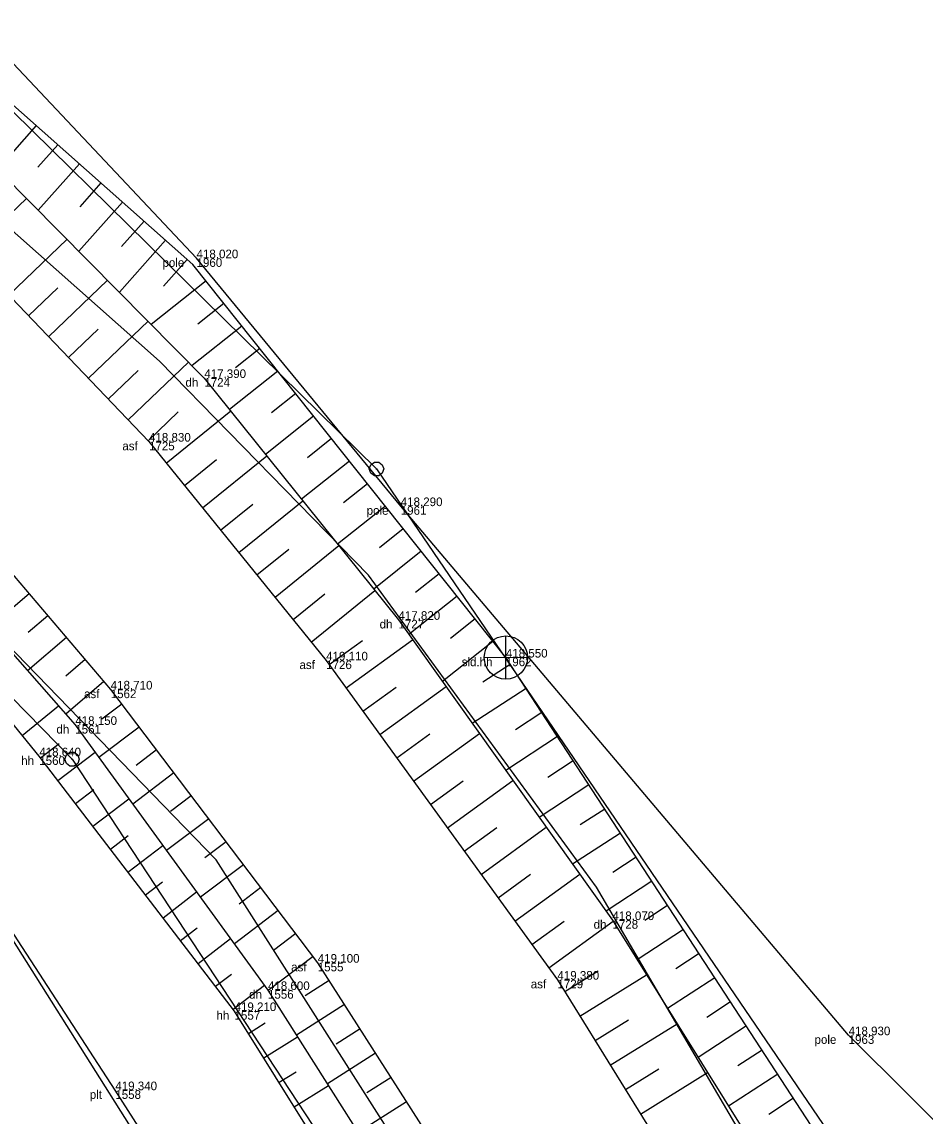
# Model space of a CAD drawing. Extents: x -747792 to -745414, y -1093712 to -1091463.
# Drawn here: x -746733.26 to -746701.9, y -1092442.69 to -1092404.68 of the extents above; entities that cross this region are included whole.
import ezdxf

# ---------------------------------------------------------------- set-up
doc = ezdxf.new("R2010")
doc.units = 0
for name, color, linetype in [('Doplňující texty', 7, 'Continuous'), ('Hladina', 7, 'Continuous'), ('Nezařazené objekty', 7, 'Continuous'), ('Nivelační značky_hrany', 7, 'Continuous'), ('Pracovní_bod JDTM STC_VC - výška', 7, 'Continuous'), ('Pracovní_bod PPBP', 7, 'Continuous'), ('Rozhraní ploch', 7, 'Continuous'), ('Stromy_porost', 7, 'Continuous'), ('Výškopis', 7, 'Continuous'), ('Čísla popisná_parcelní', 7, 'Continuous')]:
    doc.layers.add(name, color=color, linetype=linetype)

msp = doc.modelspace()

# ---------------------------------------------------------------- linework, layer by layer
at = {"layer": 'Doplňující texty'}
for points in [[(-746720.875, -1092419.97), (-746720.75, -1092420.065), (-746720.7, -1092420.21), (-746720.75, -1092420.355), (-746720.875, -1092420.45), (-746721.025, -1092420.45), (-746721.15, -1092420.355), (-746721.2, -1092420.21), (-746721.15, -1092420.065), (-746721.025, -1092419.97)], [(-746731.445, -1092430.05), (-746731.32, -1092430.145), (-746731.27, -1092430.29), (-746731.32, -1092430.435), (-746731.445, -1092430.53), (-746731.595, -1092430.53), (-746731.72, -1092430.435), (-746731.77, -1092430.29), (-746731.72, -1092430.145), (-746731.595, -1092430.05)]]:
    msp.add_lwpolyline(points, close=True, dxfattribs=at)
for points in [[(-746720.975, -1092420.21), (-746720.925, -1092420.21)], [(-746731.545, -1092430.29), (-746731.495, -1092430.29)]]:
    msp.add_lwpolyline(points, dxfattribs=at)
at = {"layer": 'Hladina'}
for p, q in [((-746727.2, -1092412.89), (-746727.2, -1092412.89)), ((-746726.93, -1092417.05), (-746726.93, -1092417.05)), ((-746728.85, -1092419.26), (-746728.85, -1092419.26)), ((-746720.11, -1092421.5), (-746720.11, -1092421.5)), ((-746720.19, -1092425.45), (-746720.19, -1092425.45)), ((-746716.46, -1092426.76), (-746716.46, -1092426.76)), ((-746722.7, -1092426.86), (-746722.7, -1092426.86)), ((-746730.18, -1092427.87), (-746730.18, -1092427.87)), ((-746731.41, -1092429.1), (-746731.41, -1092429.1)), ((-746732.66, -1092430.19), (-746732.66, -1092430.19)), ((-746712.76, -1092435.88), (-746712.76, -1092435.88)), ((-746722.99, -1092437.36), (-746722.99, -1092437.36)), ((-746714.67, -1092437.95), (-746714.67, -1092437.95)), ((-746724.72, -1092438.31), (-746724.72, -1092438.31)), ((-746725.88, -1092439.04), (-746725.88, -1092439.04)), ((-746704.56, -1092439.88), (-746704.56, -1092439.88)), ((-746730.02, -1092441.79), (-746730.02, -1092441.79))]:
    msp.add_line(p, q, dxfattribs=at)
at = {"layer": 'Nezařazené objekty'}
msp.add_lwpolyline([(-746689.71, -1092511.48), (-746691.52, -1092507.42), (-746698.75, -1092492.3), (-746705.08, -1092480.78), (-746714.94, -1092465.39), (-746724.32, -1092450.72), (-746730.02, -1092441.79), (-746735.89, -1092432.77), (-746739.69, -1092426.99), (-746754.65, -1092434.36)], dxfattribs=at)
at = {"layer": 'Nivelační značky_hrany'}
for points in [[(-746808.227, -1092357.17), (-746797.53, -1092364.29), (-746787.69, -1092371.13), (-746776.62, -1092378.78), (-746765.54, -1092386.79), (-746755.3, -1092394.62), (-746745.57, -1092402.66), (-746737.91, -1092409.79), (-746728.85, -1092419.26), (-746722.7, -1092426.86), (-746714.67, -1092437.95), (-746707.62, -1092449.35), (-746700.44, -1092461.3), (-746693.84, -1092472.82), (-746684.01, -1092490.2), (-746680.08, -1092497.02)], [(-746686.53, -1092499.12), (-746692.76, -1092488.22), (-746699.39, -1092476.65), (-746707.7, -1092462.24), (-746717.59, -1092445.81), (-746722.99, -1092437.36), (-746730.18, -1092427.87), (-746736.68, -1092420.23), (-746741.31, -1092415.91)]]:
    msp.add_lwpolyline(points, dxfattribs=at)
at = {"layer": 'Pracovní_bod JDTM STC_VC - výška'}
msp.add_lwpolyline([(-746666.48, -1092509.53), (-746671.18, -1092501.38), (-746679.28, -1092488.1), (-746683.01, -1092480.66), (-746691.02, -1092465.89), (-746695.91, -1092457.38), (-746697.67, -1092451.5), (-746700.29, -1092444.13), (-746704.56, -1092439.88), (-746720.11, -1092421.5), (-746727.2, -1092412.89), (-746738.25, -1092401.15), (-746749.37, -1092389.72), (-746764.79, -1092376.86), (-746776.64, -1092368.43), (-746787.43, -1092361.47), (-746799.53, -1092355.13), (-746817.34, -1092343.1), (-746824.75, -1092337.86), (-746838.2, -1092329.38), (-746851.64, -1092319.28)], dxfattribs=at)
at = {"layer": 'Pracovní_bod PPBP'}
for points in [[(-746676.31, -1092494.93), (-746679.28, -1092488.1), (-746684.61, -1092481.19), (-746692.58, -1092466.75), (-746703.9, -1092446.01), (-746716.46, -1092426.76), (-746727.325, -1092413.107), (-746739.95, -1092401.9), (-746747.98, -1092394.64), (-746752.03, -1092391.71), (-746753.83, -1092389.76), (-746758.64, -1092386.23), (-746765.82, -1092381.07), (-746787.5, -1092365.52), (-746806.41, -1092354.03)], [(-746807.12, -1092355.24), (-746796.58, -1092362.79), (-746786.63, -1092368.73), (-746775.02, -1092376.93), (-746764.6, -1092384.11), (-746753.89, -1092392.74), (-746744.6, -1092400.27), (-746734.99, -1092408.91), (-746726.93, -1092417.05), (-746720.19, -1092425.45), (-746712.76, -1092435.88), (-746705, -1092448.32), (-746698.55, -1092460.04), (-746691.76, -1092472.37), (-746682.53, -1092488.74), (-746678.42, -1092495.91)], [(-746732.762, -1092408.281), (-746734.11, -1092409.799)], [(-746732.014, -1092408.945), (-746732.709, -1092409.728)], [(-746731.266, -1092409.608), (-746732.7, -1092411.223)], [(-746730.518, -1092410.272), (-746731.256, -1092411.104)], [(-746735.103, -1092412.724), (-746733.106, -1092410.813)], [(-746729.771, -1092410.936), (-746731.289, -1092412.647)], [(-746729.023, -1092411.6), (-746729.804, -1092412.48)], [(-746733.721, -1092414.169), (-746731.698, -1092412.234)], [(-746728.275, -1092412.264), (-746729.879, -1092414.071)], [(-746727.527, -1092412.928), (-746728.351, -1092413.856)], [(-746732.338, -1092415.614), (-746730.291, -1092413.656)], [(-746726.87, -1092413.678), (-746728.771, -1092415.191)], [(-746733.029, -1092414.891), (-746732.012, -1092413.918)], [(-746726.248, -1092414.461), (-746727.156, -1092415.183)], [(-746731.647, -1092416.337), (-746730.617, -1092415.351)], [(-746730.956, -1092417.059), (-746728.884, -1092415.077)], [(-746725.625, -1092415.243), (-746727.356, -1092416.62)], [(-746725.002, -1092416.026), (-746725.841, -1092416.693)], [(-746729.573, -1092418.504), (-746727.476, -1092416.498)], [(-746730.264, -1092417.782), (-746729.222, -1092416.785)], [(-746724.38, -1092416.808), (-746726.055, -1092418.141)], [(-746742.5, -1092417.34), (-746737.93, -1092421.69), (-746731.41, -1092429.1), (-746724.72, -1092438.31), (-746719.2, -1092447.02), (-746709.7, -1092462.98), (-746701.01, -1092477.63), (-746694.64, -1092489.15), (-746688.39, -1092500.4)], [(-746723.757, -1092417.591), (-746724.593, -1092418.256)], [(-746728.882, -1092419.227), (-746727.836, -1092418.226)], [(-746728.25, -1092420.002), (-746726.014, -1092418.192)], [(-746723.134, -1092418.373), (-746724.803, -1092419.701)], [(-746689.26, -1092500.91), (-746696.41, -1092489.76), (-746702.72, -1092478.69), (-746711.35, -1092464.17), (-746720.24, -1092448.07), (-746725.88, -1092439.04), (-746732.66, -1092430.19), (-746738.76, -1092422.69), (-746743.86, -1092418.82)], [(-746722.512, -1092419.155), (-746723.344, -1092419.818)], [(-746727.621, -1092420.779), (-746726.504, -1092419.876)], [(-746726.992, -1092421.556), (-746724.762, -1092419.752)], [(-746721.889, -1092419.938), (-746723.551, -1092421.261)], [(-746721.266, -1092420.72), (-746722.096, -1092421.381)], [(-746726.363, -1092422.334), (-746725.249, -1092421.433)], [(-746725.734, -1092423.111), (-746723.51, -1092421.312)], [(-746720.644, -1092421.503), (-746722.3, -1092422.821)], [(-746720.021, -1092422.285), (-746720.847, -1092422.943)], [(-746725.104, -1092423.889), (-746723.994, -1092422.99)], [(-746724.475, -1092424.666), (-746722.259, -1092422.872)], [(-746719.398, -1092423.068), (-746721.048, -1092424.381)], [(-746718.776, -1092423.85), (-746719.599, -1092424.505)], [(-746723.217, -1092426.221), (-746721.007, -1092424.432)], [(-746733.008, -1092424.546), (-746734.386, -1092425.718)], [(-746723.846, -1092425.443), (-746722.74, -1092424.548)], [(-746718.153, -1092424.633), (-746719.825, -1092425.963)], [(-746732.36, -1092425.307), (-746733.043, -1092425.888)], [(-746717.53, -1092425.415), (-746718.387, -1092426.097)], [(-746731.712, -1092426.069), (-746733.065, -1092427.22)], [(-746722.596, -1092427.004), (-746721.441, -1092426.167)], [(-746722.009, -1092427.814), (-746719.698, -1092426.14)], [(-746716.907, -1092426.198), (-746718.662, -1092427.594)], [(-746731.064, -1092426.831), (-746731.734, -1092427.401)], [(-746716.306, -1092426.996), (-746717.256, -1092427.615)], [(-746730.416, -1092427.592), (-746731.743, -1092428.721)], [(-746721.423, -1092428.624), (-746720.27, -1092427.789)], [(-746720.836, -1092429.434), (-746718.538, -1092427.769)], [(-746715.76, -1092427.833), (-746717.625, -1092429.05)], [(-746733.25, -1092429.465), (-746731.99, -1092428.44)], [(-746729.796, -1092428.376), (-746730.486, -1092428.899)], [(-746715.213, -1092428.671), (-746716.129, -1092429.268)], [(-746729.192, -1092429.174), (-746730.588, -1092430.231)], [(-746720.25, -1092430.244), (-746719.104, -1092429.414)], [(-746719.663, -1092431.054), (-746717.377, -1092429.398)], [(-746732.62, -1092430.242), (-746731.965, -1092429.74)], [(-746714.667, -1092429.508), (-746716.464, -1092430.681)], [(-746732.012, -1092431.036), (-746730.722, -1092430.047)], [(-746728.588, -1092429.971), (-746729.295, -1092430.506)], [(-746714.12, -1092430.346), (-746715.002, -1092430.921)], [(-746727.985, -1092430.768), (-746729.413, -1092431.85)], [(-746731.404, -1092431.829), (-746730.769, -1092431.343)], [(-746719.077, -1092431.864), (-746717.937, -1092431.038)], [(-746718.491, -1092432.674), (-746716.217, -1092431.027)], [(-746713.574, -1092431.183), (-746715.303, -1092432.311)], [(-746730.796, -1092432.623), (-746729.546, -1092431.666)], [(-746727.381, -1092431.565), (-746728.103, -1092432.112)], [(-746713.028, -1092432.021), (-746713.875, -1092432.573)], [(-746726.777, -1092432.362), (-746728.237, -1092433.468)], [(-746717.904, -1092433.484), (-746716.77, -1092432.663)], [(-746717.318, -1092434.294), (-746715.056, -1092432.656)], [(-746712.481, -1092432.858), (-746714.141, -1092433.941)], [(-746730.188, -1092433.417), (-746729.573, -1092432.946)], [(-746726.173, -1092433.159), (-746726.911, -1092433.718)], [(-746729.58, -1092434.211), (-746728.37, -1092433.285)], [(-746725.569, -1092433.956), (-746727.061, -1092435.087)], [(-746711.935, -1092433.696), (-746712.748, -1092434.226)], [(-746716.731, -1092435.103), (-746715.604, -1092434.287)], [(-746716.145, -1092435.913), (-746713.896, -1092434.285)], [(-746728.971, -1092435.005), (-746728.377, -1092434.549)], [(-746724.965, -1092434.753), (-746725.719, -1092435.324)], [(-746711.388, -1092434.533), (-746712.98, -1092435.572)], [(-746728.363, -1092435.799), (-746727.195, -1092434.903)], [(-746710.842, -1092435.371), (-746711.636, -1092435.889)], [(-746724.361, -1092435.55), (-746725.886, -1092436.705)], [(-746715.558, -1092436.723), (-746714.437, -1092435.912)], [(-746714.972, -1092437.533), (-746712.738, -1092435.916)], [(-746727.755, -1092436.592), (-746727.181, -1092436.152)], [(-746710.295, -1092436.208), (-746711.902, -1092437.256)], [(-746727.147, -1092437.386), (-746726.019, -1092436.522)], [(-746723.757, -1092436.347), (-746724.528, -1092436.931)], [(-746709.749, -1092437.046), (-746710.561, -1092437.575)], [(-746723.153, -1092437.144), (-746724.711, -1092438.324)], [(-746726.539, -1092438.18), (-746725.985, -1092437.756)], [(-746714.415, -1092438.363), (-746713.259, -1092437.648)], [(-746713.889, -1092439.214), (-746711.574, -1092437.782)], [(-746725.931, -1092438.974), (-746724.843, -1092438.141)], [(-746722.597, -1092437.975), (-746723.428, -1092438.506)], [(-746709.203, -1092437.883), (-746710.843, -1092438.953)], [(-746722.059, -1092438.817), (-746723.724, -1092439.881)], [(-746708.656, -1092438.721), (-746709.485, -1092439.261)], [(-746725.394, -1092439.817), (-746724.811, -1092439.453)], [(-746721.52, -1092439.66), (-746722.355, -1092440.193)], [(-746713.363, -1092440.064), (-746712.203, -1092439.347)], [(-746712.837, -1092440.915), (-746710.515, -1092439.479)], [(-746708.11, -1092439.558), (-746709.784, -1092440.651)], [(-746724.865, -1092440.666), (-746723.691, -1092439.933)], [(-746707.563, -1092440.396), (-746708.409, -1092440.947)], [(-746720.982, -1092440.502), (-746722.654, -1092441.571)], [(-746724.335, -1092441.514), (-746723.746, -1092441.146)], [(-746712.311, -1092441.765), (-746711.148, -1092441.046)], [(-746711.785, -1092442.616), (-746709.457, -1092441.176)], [(-746707.017, -1092441.233), (-746708.725, -1092442.348)], [(-746723.805, -1092442.362), (-746722.621, -1092441.622)], [(-746720.443, -1092441.345), (-746721.281, -1092441.88)], [(-746719.905, -1092442.188), (-746721.583, -1092443.26)], [(-746706.47, -1092442.071), (-746707.333, -1092442.634)]]:
    msp.add_lwpolyline(points, dxfattribs=at)
at = {"layer": 'Stromy_porost'}
for points in [[(-746720.95, -1092420.21), (-746741.55, -1092399.95)], [(-746728.49, -1092416.47), (-746744.79, -1092401.99)], [(-746721.23, -1092423.9), (-746728.49, -1092416.47)], [(-746720.95, -1092420.21), (-746705.09, -1092443.49)], [(-746726.52, -1092433.79), (-746737.13, -1092422.85)], [(-746713.31, -1092434.74), (-746721.23, -1092423.9)], [(-746737.31, -1092424.38), (-746731.52, -1092430.29)], [(-746702.16, -1092486.44), (-746739.55, -1092427.1)], [(-746731.52, -1092430.29), (-746713.79, -1092457.29)], [(-746719.94, -1092444.11), (-746726.52, -1092433.79)], [(-746697.33, -1092462.02), (-746713.31, -1092434.74)]]:
    msp.add_lwpolyline(points, dxfattribs=at)
at = {"layer": 'Čísla popisná_parcelní'}
for p, q in [((-746716.461, -1092427.508), (-746716.46, -1092426.013)), ((-746715.708, -1092426.766), (-746717.208, -1092426.761))]:
    msp.add_line(p, q, dxfattribs=at)
msp.add_circle((-746716.46, -1092426.76), 0.75, dxfattribs=at)

# ---------------------------------------------------------------- texts
at = {"layer": 'Rozhraní ploch'}
for s, p in [(' pole', (-746728.494, -1092413.19)), ('1960', (-746727.2, -1092413.19)), (' dh', (-746727.695, -1092417.35)), ('1724', (-746726.93, -1092417.35)), (' asf', (-746729.887, -1092419.56)), ('1725', (-746728.85, -1092419.56)), (' pole', (-746721.404, -1092421.8)), ('1961', (-746720.11, -1092421.8)), (' dh', (-746720.955, -1092425.75)), ('1727', (-746720.19, -1092425.75)), (' sld.hh', (-746718.106, -1092427.06)), ('1962', (-746716.46, -1092427.06)), (' asf', (-746723.737, -1092427.16)), ('1726', (-746722.7, -1092427.16)), (' asf', (-746731.217, -1092428.17)), ('1562', (-746730.18, -1092428.17)), (' dh', (-746732.175, -1092429.4)), ('1561', (-746731.41, -1092429.4)), (' hh', (-746733.399, -1092430.49)), ('1560', (-746732.66, -1092430.49)), (' dh', (-746713.525, -1092436.18)), ('1728', (-746712.76, -1092436.18)), (' asf', (-746724.027, -1092437.66)), ('1555', (-746722.99, -1092437.66)), (' asf', (-746715.707, -1092438.25)), ('1729', (-746714.67, -1092438.25)), (' dh', (-746725.485, -1092438.61)), ('1556', (-746724.72, -1092438.61)), (' hh', (-746726.619, -1092439.34)), ('1557', (-746725.88, -1092439.34)), (' pole', (-746705.854, -1092440.18)), ('1963', (-746704.56, -1092440.18)), (' plt', (-746731.019, -1092442.09)), ('1558', (-746730.02, -1092442.09))]:
    msp.add_text(s, height=0.3, dxfattribs=at).set_placement(p)
at = {"layer": 'Výškopis'}
for s, p in [('418,020', (-746727.2, -1092412.89)), ('417,390', (-746726.93, -1092417.05)), ('418,830', (-746728.85, -1092419.26)), ('418,290', (-746720.11, -1092421.5)), ('417,820', (-746720.19, -1092425.45)), ('419,110', (-746722.7, -1092426.86)), ('418,550', (-746716.46, -1092426.76)), ('418,710', (-746730.18, -1092427.87)), ('418,150', (-746731.41, -1092429.1)), ('418,640', (-746732.66, -1092430.19)), ('418,070', (-746712.76, -1092435.88)), ('419,100', (-746722.99, -1092437.36)), ('419,380', (-746714.67, -1092437.95)), ('418,600', (-746724.72, -1092438.31)), ('419,210', (-746725.88, -1092439.04)), ('418,930', (-746704.56, -1092439.88)), ('419,340', (-746730.02, -1092441.79))]:
    msp.add_text(s, height=0.3, dxfattribs=at).set_placement(p)

doc.saveas('drawing.dxf')
